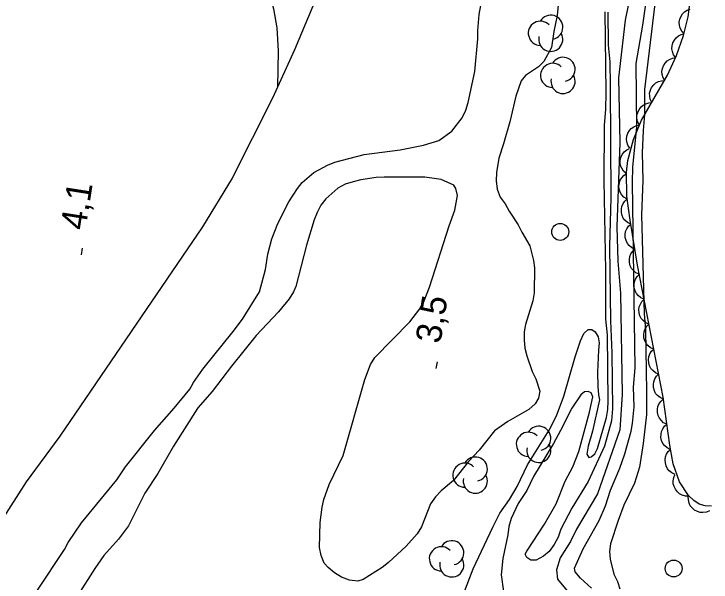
# Model space of a CAD drawing. Extents: x 282461 to 284471, y 5554090 to 5557646.
# Drawn here: x 283275.7 to 283358, y 5555047 to 5555114 of the extents above; entities that cross this region are included whole.
import ezdxf

# ---------------------------------------------------------------- set-up
doc = ezdxf.new("R2010")
doc.units = 0
for name, color, linetype in [('Niveau 2', 7, 'Continuous'), ('Niveau 22', 7, 'Continuous'), ('Niveau 3', 7, 'Continuous'), ('Niveau 36', 7, 'Continuous'), ('Niveau 4', 7, 'Continuous'), ('Niveau 44', 7, 'Continuous'), ('Niveau 7', 7, 'Continuous')]:
    doc.layers.add(name, color=color, linetype=linetype)

msp = doc.modelspace()

# ---------------------------------------------------------------- linework, layer by layer
at = {"layer": 'Niveau 2'}
for points in [[(283278.46, 5555046.01), (283281.65, 5555050.79), (283282.1, 5555051.61), (283283.64, 5555053.94), (283287.82, 5555059.02), (283288.84, 5555060.54), (283292.27, 5555064.86), (283294.62, 5555067.49), (283296.45, 5555069.71), (283296.9, 5555070.53), (283297.99, 5555072.1), (283301.59, 5555076.54), (283302.68, 5555078), (283304.67, 5555081.21), (283305.39, 5555083.88), (283305.66, 5555085.68), (283306.16, 5555087.48), (283306.84, 5555089.29), (283308.14, 5555091.85), (283309.17, 5555093.43), (283309.74, 5555094.13), (283311.12, 5555095.3), (283312.73, 5555096.19), (283313.6, 5555096.54), (283317.07, 5555097.45), (283321.3, 5555098.01), (283324.08, 5555098.56), (283325.87, 5555099.1), (283327.43, 5555100.21), (283328.63, 5555101.79), (283329.08, 5555102.67), (283329.36, 5555103.6), (283330.13, 5555107.26), (283330.49, 5555111.09), (283330.48, 5555112.07), (283330.63, 5555113.99), (283330.96, 5555115.67)], [(283340.01, 5555115.52), (283339.85, 5555113.84), (283339.47, 5555111.98), (283339.2, 5555110.06), (283338.29, 5555108.43), (283337.66, 5555107.78), (283336.1, 5555106.78), (283335.59, 5555106.14), (283334.97, 5555104.33), (283334.25, 5555101.31), (283333.52, 5555098.69), (283332.96, 5555097), (283332.69, 5555095.32), (283332.65, 5555094.33), (283332.77, 5555093.35), (283333.13, 5555092.42), (283333.72, 5555091.62), (283334.2, 5555090.75), (283335.26, 5555089.14), (283335.68, 5555088.27), (283336.63, 5555086.65), (283337.06, 5555084.92), (283337.18, 5555084.05), (283337.16, 5555081.09), (283337, 5555080.16), (283336.1, 5555077.37), (283335.94, 5555076.49), (283335.95, 5555075.57), (283336.02, 5555074.58), (283336.26, 5555073.65), (283336.92, 5555071.8), (283337.34, 5555070.94), (283337.82, 5555069.49), (283337.66, 5555068.68), (283337.26, 5555067.98), (283336.51, 5555067.33), (283334.03, 5555065.92), (283332.47, 5555064.8), (283330.64, 5555062.52), (283329.38, 5555061.17), (283327.61, 5555058.95), (283326.17, 5555057.72), (283325.48, 5555057.02), (283324.91, 5555056.2), (283323.84, 5555053.46), (283323.32, 5555052.64), (283322.01, 5555051.18), (283319.94, 5555049.25), (283319.19, 5555048.66), (283316.94, 5555047.25), (283316.3, 5555047.07), (283315.32, 5555047.17), (283314.38, 5555047.51)], [(283351.4, 5555115.23), (283350.18, 5555105.11), (283350.16, 5555102.15), (283350, 5555100.29), (283349.92, 5555097.62), (283349.96, 5555094.36), (283349.83, 5555090.3), (283350.14, 5555078.63), (283350.28, 5555076.77), (283350.43, 5555069.46), (283350.4, 5555066.73), (283350.03, 5555063.3), (283349.6, 5555060.51), (283348.98, 5555058.64), (283347.74, 5555056.02), (283347.06, 5555054.21), (283346.16, 5555051.48), (283346.06, 5555050.55), (283346.12, 5555049.67), (283346.55, 5555047.88), (283346.97, 5555047.01), (283347.27, 5555046.14)], [(283343.36, 5555062.07), (283343.6, 5555061.67), (283343.89, 5555061.73), (283344.29, 5555062.08), (283344.63, 5555062.72), (283345.69, 5555066.39), (283345.86, 5555067.32), (283345.9, 5555068.31), (283345.81, 5555076.15), (283345.61, 5555078.01), (283345.61, 5555083.75), (283345.42, 5555094.38), (283345.46, 5555100.88), (283345.61, 5555102.8), (283345.65, 5555104.78), (283345.53, 5555114.3)], [(283314.38, 5555047.51), (283313.56, 5555048.03), (283312.8, 5555048.66), (283312.33, 5555049.17), (283311.97, 5555050.1), (283311.78, 5555051.02), (283311.87, 5555053.98), (283312.08, 5555055.78), (283312.3, 5555056.71), (283312.92, 5555058.46), (283314.56, 5555061.9), (283317.13, 5555070.86), (283317.8, 5555072.66), (283318.31, 5555073.48), (283322.45, 5555077.7), (283323.65, 5555079.22), (283324.05, 5555079.98), (283324.78, 5555081.78), (283327.08, 5555089), (283327.75, 5555090.86), (283328.08, 5555092.6), (283327.89, 5555093.41), (283327.66, 5555093.82), (283326.14, 5555094.5), (283324.22, 5555094.77), (283319.4, 5555094.78), (283318.47, 5555094.71), (283316.67, 5555094.46), (283315.74, 5555094.22), (283314.82, 5555093.92), (283313.95, 5555093.45), (283312.52, 5555092.22), (283311.94, 5555091.46), (283311.49, 5555090.59), (283311.15, 5555089.71), (283310.26, 5555086.74), (283308.98, 5555081.86), (283308.7, 5555081.22), (283308.18, 5555080.4), (283306.92, 5555078.88), (283304.29, 5555076.07), (283301.37, 5555072.45), (283299.08, 5555069.46), (283297.42, 5555067.53), (283294.51, 5555062.98), (283292.69, 5555059.77), (283291.15, 5555057.44), (283289.22, 5555053.59), (283288.02, 5555052.01), (283286.3, 5555050.08), (283285.22, 5555048.57), (283283.22, 5555045.41)], [(283328.85, 5555045.62), (283329.92, 5555048.53), (283332.24, 5555053.43), (283333.1, 5555055.07), (283334.24, 5555056.7), (283335.15, 5555058.22), (283336.34, 5555060.79), (283338.91, 5555064.88), (283339.76, 5555066.57), (283340.66, 5555068.9), (283342, 5555073.56), (283342.62, 5555075.42), (283343.02, 5555076.3), (283343.54, 5555076.77), (283343.94, 5555076.77), (283344.35, 5555076.48), (283344.71, 5555075.91), (283344.83, 5555075.21), (283344.73, 5555074.34), (283344.64, 5555071.72), (283344.66, 5555070.04), (283344.73, 5555069.05), (283344.86, 5555068.48), (283344.03, 5555064.75), (283343.52, 5555063), (283343.36, 5555062.07)]]:
    msp.add_lwpolyline(points, dxfattribs=at)
at = {"layer": 'Niveau 22'}
for points in [[(283335.91, 5555171.82), (283334.84, 5555169.15), (283332.18, 5555163.38), (283327.66, 5555153.19), (283325.67, 5555149.57), (283323.29, 5555144.68), (283318.27, 5555132.86), (283311.83, 5555116.96), (283308.84, 5555109.8), (283306.24, 5555104.09), (283301.47, 5555094.66), (283297.95, 5555088.89), (283281.08, 5555064.16), (283277.14, 5555058.79), (283272.92, 5555052.26)], [(283291.68, 5555137.37), (283297.69, 5555129.68), (283301.53, 5555124.27), (283303.24, 5555121.74), (283305.87, 5555116.44), (283306.35, 5555114.65), (283306.73, 5555112.39), (283306.88, 5555109.67), (283306.82, 5555105.38)]]:
    msp.add_lwpolyline(points, dxfattribs=at)
at = {"layer": 'Niveau 3'}
for p, q in [((283283.64, 5555085.58), (283283.76, 5555086.37)), ((283325.58, 5555072.18), (283325.7, 5555072.97))]:
    msp.add_line(p, q, dxfattribs=at)
at = {"layer": 'Niveau 36'}
for centre in [(283340.22, 5555088.297), (283353.619, 5555048.548)]:
    msp.add_circle(centre, 1, dxfattribs=at)
at = {"layer": 'Niveau 4'}
msp.add_lwpolyline([(283348.28, 5555115.23), (283347.9, 5555113.31), (283347.11, 5555106.5), (283347.26, 5555098.84), (283346.91, 5555088.9), (283347.01, 5555084.84), (283347.35, 5555081.07), (283347.55, 5555069.1), (283347.25, 5555064.92), (283344.61, 5555057.35), (283342.15, 5555053.2), (283341.42, 5555051.74), (283340.22, 5555049.81), (283339.77, 5555048.41), (283339.9, 5555047.31), (283342.02, 5555044.72)], dxfattribs=at)
at = {"layer": 'Niveau 44'}
for points in [[(283358.08, 5555055.93), (283357.36, 5555055.96), (283356.65, 5555056.16), (283356, 5555056.58), (283355.39, 5555057.18), (283354.32, 5555058.79), (283353.57, 5555060.91), (283353.15, 5555063.12), (283352.37, 5555068.77), (283349.36, 5555084.38), (283348.48, 5555089.69), (283348.07, 5555092.52), (283348.03, 5555095.35), (283348.21, 5555096.72), (283348.88, 5555099.22), (283349.84, 5555101.5), (283352.9, 5555106.83), (283353.96, 5555109.15), (283354.8, 5555111.5), (283355.34, 5555113.71), (283355.59, 5555115.53)], [(283354.85, 5555111.71), (283354.57, 5555112.02), (283354.4, 5555112.38), (283354.3, 5555112.7), (283354.29, 5555113.05), (283354.35, 5555113.42), (283354.5, 5555113.77), (283354.66, 5555114.05), (283354.92, 5555114.29), (283355.23, 5555114.5), (283355.56, 5555114.62)], [(283353.86, 5555108.87), (283353.61, 5555109.21), (283353.48, 5555109.59), (283353.41, 5555109.92), (283353.44, 5555110.27), (283353.54, 5555110.63), (283353.72, 5555110.96), (283353.91, 5555111.23), (283354.19, 5555111.44), (283354.52, 5555111.61), (283354.87, 5555111.7)], [(283352.59, 5555106.15), (283352.37, 5555106.51), (283352.27, 5555106.9), (283352.23, 5555107.23), (283352.29, 5555107.58), (283352.42, 5555107.93), (283352.63, 5555108.24), (283352.84, 5555108.49), (283353.14, 5555108.68), (283353.48, 5555108.82), (283353.84, 5555108.88)], [(283351.03, 5555103.58), (283350.85, 5555103.96), (283350.79, 5555104.36), (283350.78, 5555104.69), (283350.87, 5555105.03), (283351.02, 5555105.36), (283351.27, 5555105.66), (283351.5, 5555105.89), (283351.82, 5555106.05), (283352.17, 5555106.16), (283352.53, 5555106.18)], [(283349.54, 5555100.98), (283349.36, 5555101.35), (283349.29, 5555101.75), (283349.28, 5555102.08), (283349.37, 5555102.42), (283349.53, 5555102.76), (283349.77, 5555103.06), (283350.01, 5555103.28), (283350.32, 5555103.44), (283350.68, 5555103.55), (283351.03, 5555103.58)], [(283348.44, 5555098.18), (283348.21, 5555098.53), (283348.1, 5555098.92), (283348.05, 5555099.25), (283348.1, 5555099.59), (283348.21, 5555099.95), (283348.42, 5555100.27), (283348.62, 5555100.52), (283348.91, 5555100.72), (283349.25, 5555100.87), (283349.61, 5555100.94)], [(283348.01, 5555095.19), (283347.7, 5555095.47), (283347.48, 5555095.81), (283347.35, 5555096.11), (283347.3, 5555096.46), (283347.32, 5555096.83), (283347.43, 5555097.2), (283347.56, 5555097.5), (283347.79, 5555097.77), (283348.08, 5555098), (283348.4, 5555098.16)], [(283348.07, 5555092.19), (283347.73, 5555092.41), (283347.46, 5555092.73), (283347.29, 5555093.01), (283347.19, 5555093.35), (283347.16, 5555093.71), (283347.22, 5555094.09), (283347.3, 5555094.41), (283347.49, 5555094.7), (283347.74, 5555094.98), (283348.03, 5555095.19)], [(283348.55, 5555089.22), (283348.17, 5555089.4), (283347.87, 5555089.68), (283347.66, 5555089.93), (283347.52, 5555090.25), (283347.44, 5555090.61), (283347.45, 5555091), (283347.49, 5555091.32), (283347.64, 5555091.64), (283347.85, 5555091.95), (283348.12, 5555092.19)], [(283349.05, 5555086.26), (283348.67, 5555086.43), (283348.36, 5555086.7), (283348.15, 5555086.95), (283348, 5555087.27), (283347.91, 5555087.63), (283347.91, 5555088.01), (283347.95, 5555088.34), (283348.09, 5555088.66), (283348.3, 5555088.97), (283348.56, 5555089.22)], [(283349.54, 5555083.3), (283349.16, 5555083.47), (283348.86, 5555083.74), (283348.64, 5555083.99), (283348.49, 5555084.31), (283348.4, 5555084.67), (283348.4, 5555085.05), (283348.44, 5555085.38), (283348.58, 5555085.7), (283348.79, 5555086.01), (283349.05, 5555086.26)], [(283350.14, 5555080.35), (283349.75, 5555080.52), (283349.44, 5555080.78), (283349.22, 5555081.02), (283349.07, 5555081.34), (283348.96, 5555081.7), (283348.96, 5555082.08), (283348.98, 5555082.41), (283349.12, 5555082.73), (283349.31, 5555083.05), (283349.57, 5555083.3)], [(283350.7, 5555077.41), (283350.32, 5555077.57), (283350.01, 5555077.83), (283349.79, 5555078.08), (283349.63, 5555078.39), (283349.53, 5555078.75), (283349.52, 5555079.13), (283349.55, 5555079.46), (283349.69, 5555079.78), (283349.88, 5555080.1), (283350.14, 5555080.35)], [(283351.27, 5555074.46), (283350.89, 5555074.62), (283350.58, 5555074.88), (283350.36, 5555075.13), (283350.2, 5555075.45), (283350.1, 5555075.8), (283350.09, 5555076.18), (283350.12, 5555076.51), (283350.25, 5555076.84), (283350.45, 5555077.15), (283350.7, 5555077.41)], [(283351.84, 5555071.51), (283351.46, 5555071.67), (283351.15, 5555071.94), (283350.92, 5555072.18), (283350.77, 5555072.5), (283350.67, 5555072.85), (283350.66, 5555073.24), (283350.69, 5555073.56), (283350.82, 5555073.89), (283351.02, 5555074.2), (283351.27, 5555074.46)], [(283352.41, 5555068.56), (283352.03, 5555068.73), (283351.71, 5555068.99), (283351.49, 5555069.23), (283351.34, 5555069.55), (283351.24, 5555069.91), (283351.23, 5555070.29), (283351.26, 5555070.61), (283351.39, 5555070.94), (283351.59, 5555071.26), (283351.84, 5555071.51)], [(283352.81, 5555065.59), (283352.43, 5555065.77), (283352.14, 5555066.05), (283351.93, 5555066.31), (283351.79, 5555066.63), (283351.71, 5555066.99), (283351.72, 5555067.37), (283351.77, 5555067.7), (283351.92, 5555068.02), (283352.13, 5555068.32), (283352.4, 5555068.56)], [(283353.22, 5555062.61), (283352.84, 5555062.8), (283352.55, 5555063.08), (283352.34, 5555063.33), (283352.2, 5555063.66), (283352.12, 5555064.02), (283352.13, 5555064.4), (283352.18, 5555064.72), (283352.33, 5555065.04), (283352.54, 5555065.35), (283352.81, 5555065.59)], [(283353.81, 5555059.67), (283353.42, 5555059.83), (283353.11, 5555060.1), (283352.89, 5555060.34), (283352.74, 5555060.66), (283352.64, 5555061.01), (283352.63, 5555061.4), (283352.66, 5555061.72), (283352.79, 5555062.05), (283352.99, 5555062.36), (283353.25, 5555062.62)], [(283355.44, 5555057.11), (283355.02, 5555057.11), (283354.63, 5555057.23), (283354.33, 5555057.37), (283354.07, 5555057.61), (283353.84, 5555057.9), (283353.68, 5555058.25), (283353.58, 5555058.56), (283353.58, 5555058.91), (283353.64, 5555059.28), (283353.77, 5555059.61)], [(283357.87, 5555055.37), (283357.49, 5555055.21), (283357.08, 5555055.16), (283356.75, 5555055.17), (283356.42, 5555055.28), (283356.09, 5555055.45), (283355.81, 5555055.71), (283355.59, 5555055.96), (283355.45, 5555056.28), (283355.36, 5555056.64), (283355.35, 5555057)]]:
    msp.add_lwpolyline(points, dxfattribs=at)
for centre, start, end in [((283339.1, 5555112.472), 282.26917, 149.72625), ((283337.872, 5555111.758), 44.11537, 269.80396), ((283339.1, 5555111.045), 166.93686, 29.62122), ((283340.553, 5555107.497), 282.26917, 149.72625), ((283339.325, 5555106.783), 44.11537, 269.80396), ((283340.553, 5555106.07), 166.93686, 29.62122), ((283337.684, 5555063.923), 282.26917, 149.72625), ((283336.456, 5555063.209), 44.11537, 269.80396), ((283337.684, 5555062.496), 166.93686, 29.62122), ((283328.964, 5555059.578), 44.11537, 269.80396), ((283330.191, 5555060.291), 282.26917, 149.72625), ((283330.191, 5555058.864), 166.93686, 29.62122), ((283326.177, 5555049.69), 44.11537, 269.80396), ((283327.405, 5555050.404), 282.26917, 149.72625), ((283327.405, 5555048.976), 166.93686, 29.62122)]:
    msp.add_arc(centre, 1.427, start, end, dxfattribs=at)
at = {"layer": 'Niveau 7'}
for points in [[(283344.82, 5555054.21), (283345.55, 5555055.96), (283346.17, 5555057.82), (283347.25, 5555060.39), (283347.87, 5555062.08), (283348.59, 5555064.75), (283348.75, 5555065.69), (283348.96, 5555067.66), (283348.88, 5555069.98), (283349.08, 5555072.25), (283348.77, 5555094.09), (283348.8, 5555096), (283349.27, 5555100.65), (283349.18, 5555108.2), (283349.99, 5555112.73), (283350.36, 5555115.47)], [(283345.84, 5555114.26), (283345.88, 5555110.37), (283346.08, 5555108.4), (283346.12, 5555105.61), (283346.21, 5555092.37), (283346.05, 5555086.56), (283346.15, 5555077.79), (283346.31, 5555074.02), (283346.39, 5555067.4), (283346.29, 5555066), (283345.47, 5555062.98), (283343.54, 5555058.84), (283341.6, 5555055.69), (283340.3, 5555053.18), (283339.96, 5555052.24), (283339.5, 5555051.37), (283338.93, 5555050.55), (283338.24, 5555050.02), (283337.37, 5555049.55), (283336.73, 5555049.54), (283336.26, 5555049.83), (283336.09, 5555050.23), (283336.26, 5555050.58), (283338.37, 5555053.8), (283339.74, 5555056.19), (283340.81, 5555058.87), (283341.72, 5555060.57), (283342.4, 5555062.37), (283343.68, 5555067.03), (283344.06, 5555068.83), (283343.88, 5555069.3), (283343.53, 5555069.47), (283343.07, 5555069.41), (283342.67, 5555069.05), (283341.58, 5555067.47), (283340.27, 5555064.85), (283339.42, 5555063.33), (283337.08, 5555059.42), (283336.29, 5555057.78), (283335.26, 5555056.21), (283334.41, 5555054.46), (283334.13, 5555053.52), (283334.02, 5555052.54), (283333.42, 5555049.74), (283333.26, 5555047.82), (283333.52, 5555045.85)], [(283343.92, 5555046.24), (283342.63, 5555047.39), (283341.98, 5555048.14), (283341.92, 5555048.6), (283342.94, 5555050.88), (283344.82, 5555054.21)]]:
    msp.add_lwpolyline(points, dxfattribs=at)

# ---------------------------------------------------------------- texts
at = {"layer": 'Niveau 3'}
for s, p in [('4,1  ', (283284.12, 5555088.42)), ('3,5  ', (283326.06, 5555075.02))]:
    msp.add_text(s, height=3, rotation=81.09575, dxfattribs=at).set_placement(p)

doc.saveas('drawing.dxf')
